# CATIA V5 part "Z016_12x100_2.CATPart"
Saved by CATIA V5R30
Part number: SIKMY KOLIK KUZELOVY 18° D12
Bounding box of the stored display mesh (mm): x -6 to 94, y -8 to 8, z -8 to 8
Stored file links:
  C:\Users\ondra\Desktop\PŘÍLOHA P III\CATIA\Z016_12x100_2.CATPart
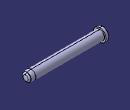
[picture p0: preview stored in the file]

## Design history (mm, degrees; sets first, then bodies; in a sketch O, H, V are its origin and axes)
Set1
  DatumSurface1 to DatumSurface14 "Z016/12x"
  Point1: type OnSurface, Support DatumSurface14, Length 0, Direction edge of DatumSurface13
  Plane1: type Tangent, Support DatumSurface14, RefPoint Point1
  Join1: Elements (DatumSurface1; DatumSurface2; DatumSurface3; DatumSurface4; DatumSurface5; DatumSurface6; DatumSurface7; DatumSurface8; DatumSurface9; DatumSurface10; DatumSurface11; DatumSurface12; DatumSurface13; DatumSurface14)
Body1 (main body)
  CloseSurface1: CloseElement Join1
